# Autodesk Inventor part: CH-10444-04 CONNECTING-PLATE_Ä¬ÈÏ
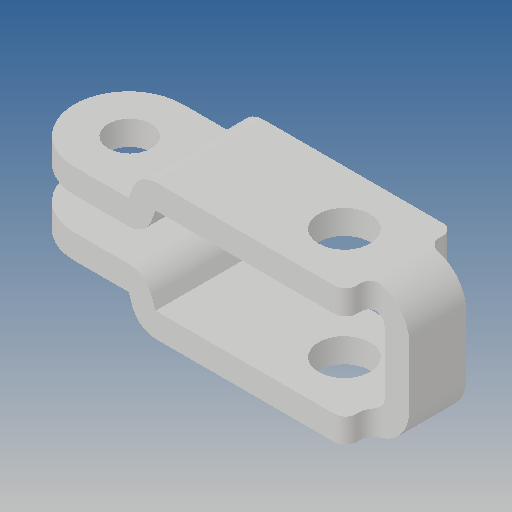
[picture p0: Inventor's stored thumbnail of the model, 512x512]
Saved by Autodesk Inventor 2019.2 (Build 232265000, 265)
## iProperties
Created: 2010-06
Part Number: CH-10444-04 CONNECTING-PLATE_Ä¬ÈÏ
Material: Ogólny
Document SubType Name: Modeling
Designer: CADENGINEERING4
Density: 1 g/cm^3
Appearance: Domyślna
Author: CADENGINEERING4
Revision Number: ÈÎºÎ
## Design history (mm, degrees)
feature "NONE"
node "Bryła1"
